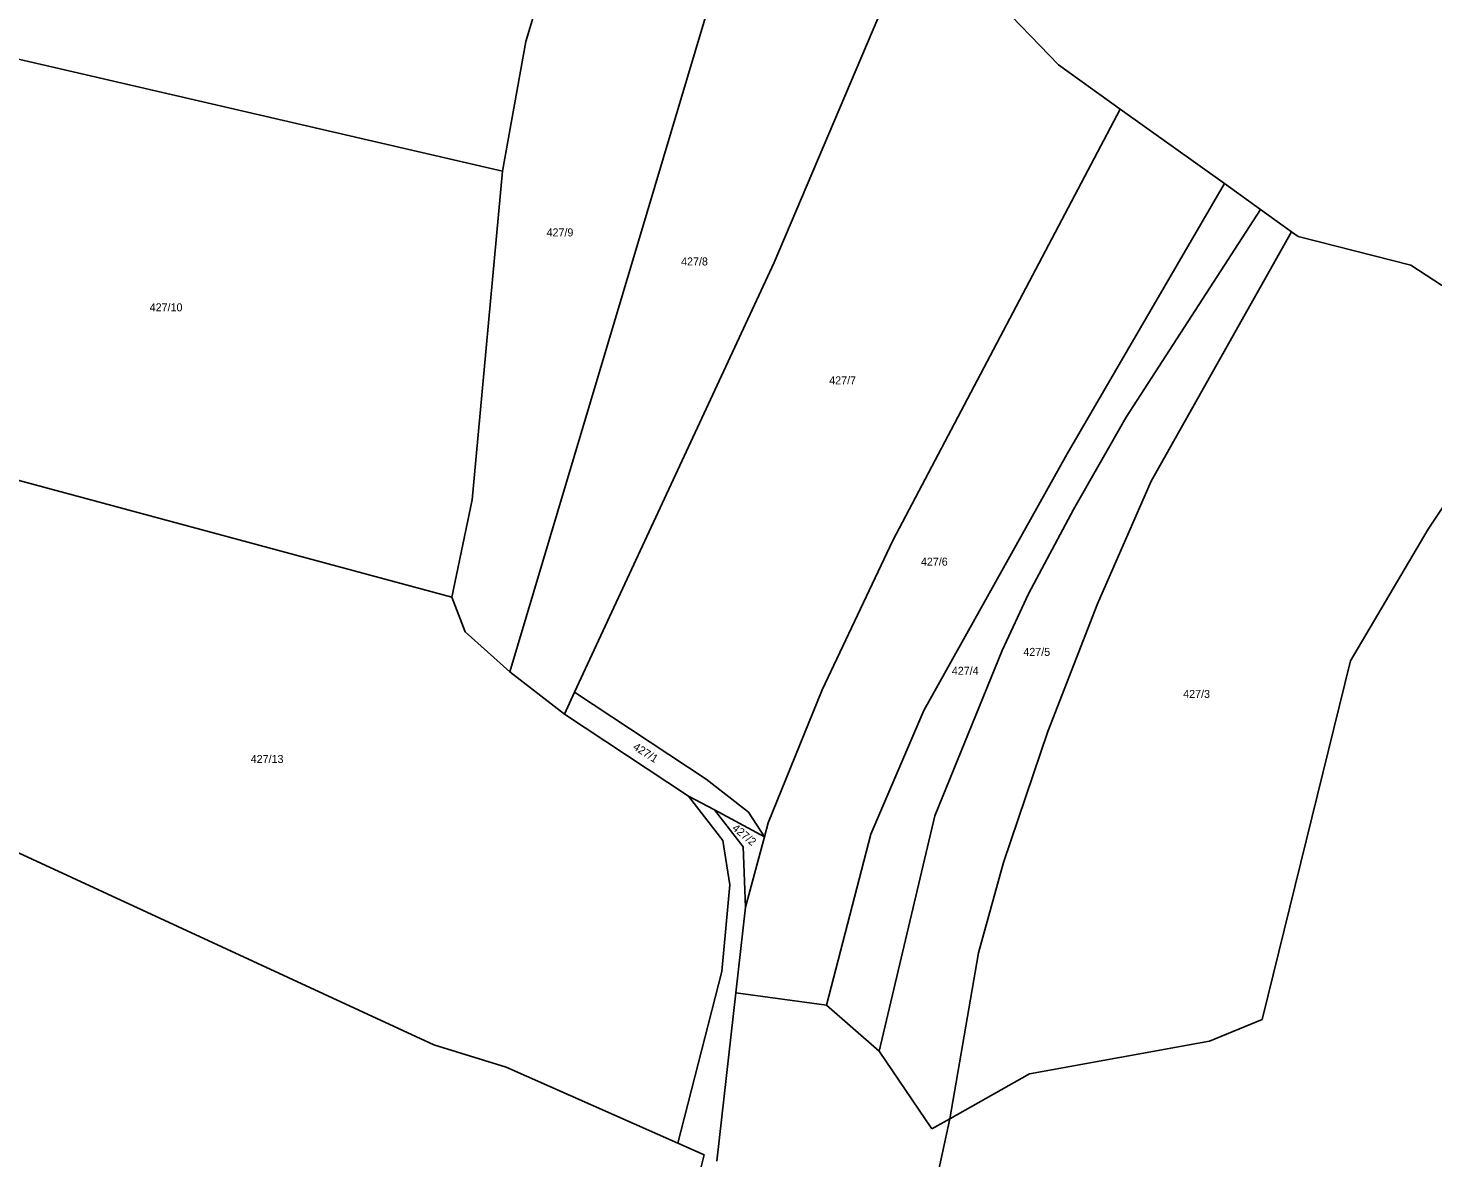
# Model space of a CAD drawing. Extents: x -791032 to -787751, y -1106872 to -1104403.
# Drawn here: x -789231 to -788932.6, y -1104939.4 to -1104699.4 of the extents above; entities that cross this region are included whole.
import ezdxf

# ---------------------------------------------------------------- set-up
doc = ezdxf.new("R2010")
doc.units = 0
for name, color, linetype in [('Vrstva 1', 7, 'Continuous'), ('Vrstva 14', 7, 'Continuous'), ('Vrstva 4', 7, 'Continuous')]:
    doc.layers.add(name, color=color, linetype=linetype)

msp = doc.modelspace()

# ---------------------------------------------------------------- linework, layer by layer
at = {"layer": 'Vrstva 1'}
for p, q in [((-789080.05, -1104673.26), (-789128.69, -1104836.15)), ((-789125.35, -1104702.3), (-789118.21, -1104678.29)), ((-789072.58, -1104749.18), (-789050.55, -1104697.36)), ((-789252.66, -1104701.48), (-789130.29, -1104729.79)), ((-789130.29, -1104729.79), (-789125.35, -1104702.3)), ((-789047.39, -1104808.29), (-788999.08, -1104716.61)), ((-789136.7, -1104799.59), (-789130.29, -1104729.79)), ((-788976.93, -1104732.46), (-789010.35, -1104789.82)), ((-788969.27, -1104737.94), (-788997.81, -1104782.03)), ((-788962.66, -1104742.67), (-788992.48, -1104795.66)), ((-789114.96, -1104840.47), (-789072.58, -1104749.18)), ((-788933.68, -1104805.84), (-788908.74, -1104768.35)), ((-789008.99, -1104801.7), (-788997.81, -1104782.03)), ((-789010.35, -1104789.82), (-789040.81, -1104844.37)), ((-789248.58, -1104791.34), (-789141.03, -1104820.32)), ((-789003.88, -1104821.71), (-788992.48, -1104795.66)), ((-789141.03, -1104820.32), (-789136.7, -1104799.59)), ((-789018.55, -1104819.57), (-789008.99, -1104801.7)), ((-789062.39, -1104839.97), (-789047.39, -1104808.29)), ((-788950.11, -1104833.83), (-788933.68, -1104805.84)), ((-789141.03, -1104820.32), (-789138.2, -1104827.64)), ((-789024.12, -1104831.62), (-789018.55, -1104819.57)), ((-789014.43, -1104848.87), (-789003.88, -1104821.71)), ((-789138.2, -1104827.64), (-789128.69, -1104836.15)), ((-789038.42, -1104866.76), (-789024.12, -1104831.62)), ((-788968.91, -1104910.02), (-788950.11, -1104833.83)), ((-789128.69, -1104836.15), (-789117.12, -1104845.12)), ((-789117.12, -1104845.12), (-789114.96, -1104840.47)), ((-789114.96, -1104840.47), (-789087.02, -1104858.97)), ((-789073.81, -1104868.25), (-789062.39, -1104839.97)), ((-789052, -1104870.67), (-789040.81, -1104844.37)), ((-789117.12, -1104845.12), (-789090.73, -1104862.58)), ((-789023.87, -1104876.69), (-789014.43, -1104848.87)), ((-789087.02, -1104858.97), (-789078.04, -1104866)), ((-789144.83, -1104915.36), (-789254.72, -1104864.68)), ((-789090.73, -1104862.58), (-789085.25, -1104865.5)), ((-789083.5, -1104872.02), (-789090.73, -1104862.58)), ((-789085.25, -1104865.5), (-789079.12, -1104873.32)), ((-789074.6, -1104871.18), (-789085.25, -1104865.5)), ((-789078.04, -1104866), (-789074.6, -1104871.18)), ((-789074.6, -1104871.18), (-789073.81, -1104868.25)), ((-789050.27, -1104916.74), (-789038.42, -1104866.76)), ((-789078.64, -1104886.15), (-789074.6, -1104871.18)), ((-789061.42, -1104907), (-789052, -1104870.67)), ((-789081.99, -1104881.38), (-789083.5, -1104872.02)), ((-789079.12, -1104873.32), (-789078.64, -1104886.15)), ((-789029.13, -1104895.85), (-789023.87, -1104876.69)), ((-789083.7, -1104899.83), (-789081.99, -1104881.38)), ((-789078.64, -1104886.15), (-789080.69, -1104904.37)), ((-789035.27, -1104931.1), (-789029.13, -1104895.85)), ((-789093.02, -1104936.28), (-789083.7, -1104899.83)), ((-789080.69, -1104904.37), (-789084.72, -1104940.08)), ((-789061.42, -1104907), (-789080.69, -1104904.37)), ((-789061.42, -1104907), (-789050.27, -1104916.74)), ((-788980.07, -1104914.59), (-788968.91, -1104910.02)), ((-789129.53, -1104920.13), (-789144.83, -1104915.36)), ((-789018.36, -1104921.53), (-788980.07, -1104914.59)), ((-789050.27, -1104916.74), (-789039.11, -1104933.27)), ((-789093.02, -1104936.28), (-789129.53, -1104920.13)), ((-789035.27, -1104931.1), (-789018.36, -1104921.53)), ((-789048.55, -1104991.98), (-789035.27, -1104931.1)), ((-789039.11, -1104933.27), (-789035.27, -1104931.1)), ((-789087.45, -1104938.74), (-789093.02, -1104936.28)), ((-789103.68, -1105002.93), (-789087.45, -1104938.74))]:
    msp.add_line(p, q, dxfattribs=at)
at = {"layer": 'Vrstva 4'}
for p, q in [((-789012.2, -1104707.23), (-789026.32, -1104692.54)), ((-788999.08, -1104716.61), (-789012.2, -1104707.23)), ((-788976.93, -1104732.46), (-788999.08, -1104716.61)), ((-788969.27, -1104737.94), (-788976.93, -1104732.46)), ((-788962.66, -1104742.67), (-788969.27, -1104737.94)), ((-788961.28, -1104743.66), (-788962.66, -1104742.67)), ((-788937.35, -1104749.81), (-788961.28, -1104743.66)), ((-788937.35, -1104749.81), (-788908.74, -1104768.35))]:
    msp.add_line(p, q, dxfattribs=at)

# ---------------------------------------------------------------- texts
at = {"layer": 'Vrstva 14'}
for s, p in [('427/9', (-789120.912, -1104743.67)), ('427/8', (-789092.332, -1104749.84)), ('427/10', (-789205.214, -1104759.58)), ('427/7', (-789060.869, -1104775.1)), ('427/6', (-789041.392, -1104813.61)), ('427/5', (-789019.638, -1104832.78)), ('427/4', (-789034.828, -1104836.79)), ('427/3', (-788985.682, -1104841.71)), ('427/13', (-789183.755, -1104855.52))]:
    msp.add_text(s, height=1.7, dxfattribs=at).set_placement(p)
for s, rotation, p in [('427/1', 327.34341, (-789102.708, -1104852.502)), ('427/2', 320.34213, (-789081.646, -1104869.604))]:
    msp.add_text(s, height=1.7, rotation=rotation, dxfattribs=at).set_placement(p)

doc.saveas('drawing.dxf')
